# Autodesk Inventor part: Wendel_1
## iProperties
Created: 2009-08
Part Number: Wendel_1
Document SubType Name: Modeling
Density: 1 g/cm^3
Author: dreamlab
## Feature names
1. Coil1
2. Rectangular Pattern1
3. Rectangular Pattern2
4. Extrusion1
5. Extrusion2
6. Extrusion3
